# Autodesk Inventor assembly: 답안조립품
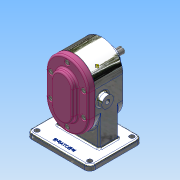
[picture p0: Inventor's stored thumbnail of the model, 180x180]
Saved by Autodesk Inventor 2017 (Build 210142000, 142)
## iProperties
Part Number: 답안조립품
Material: 일반
Document SubType Name: Assembly
Designer: 222
Author: 222
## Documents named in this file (11)
- C:\Users\222\Desktop\700906V1043\답안조립품.iam
- C:\Users\222\Desktop\700906V1043\본체.ipt
- C:\Users\222\Desktop\700906V1043\개스킷.ipt
- C:\Users\222\Desktop\700906V1043\메인축.ipt
- C:\Users\222\Desktop\700906V1043\베어링부시.ipt
- C:\Users\222\Desktop\700906V1043\볼트 M5.ipt
- C:\Users\222\Desktop\700906V1043\서브축.ipt
- C:\Users\222\Desktop\700906V1043\스퍼기어.ipt
- C:\Users\222\Desktop\700906V1043\오일 실 16 28 7.ipt
- C:\Users\222\Desktop\700906V1043\커버.ipt
- C:\Users\222\Desktop\700906V1043\키 6 x 6 x 18.ipt
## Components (1 placed, 1 different names)
1. 개스킷:1
